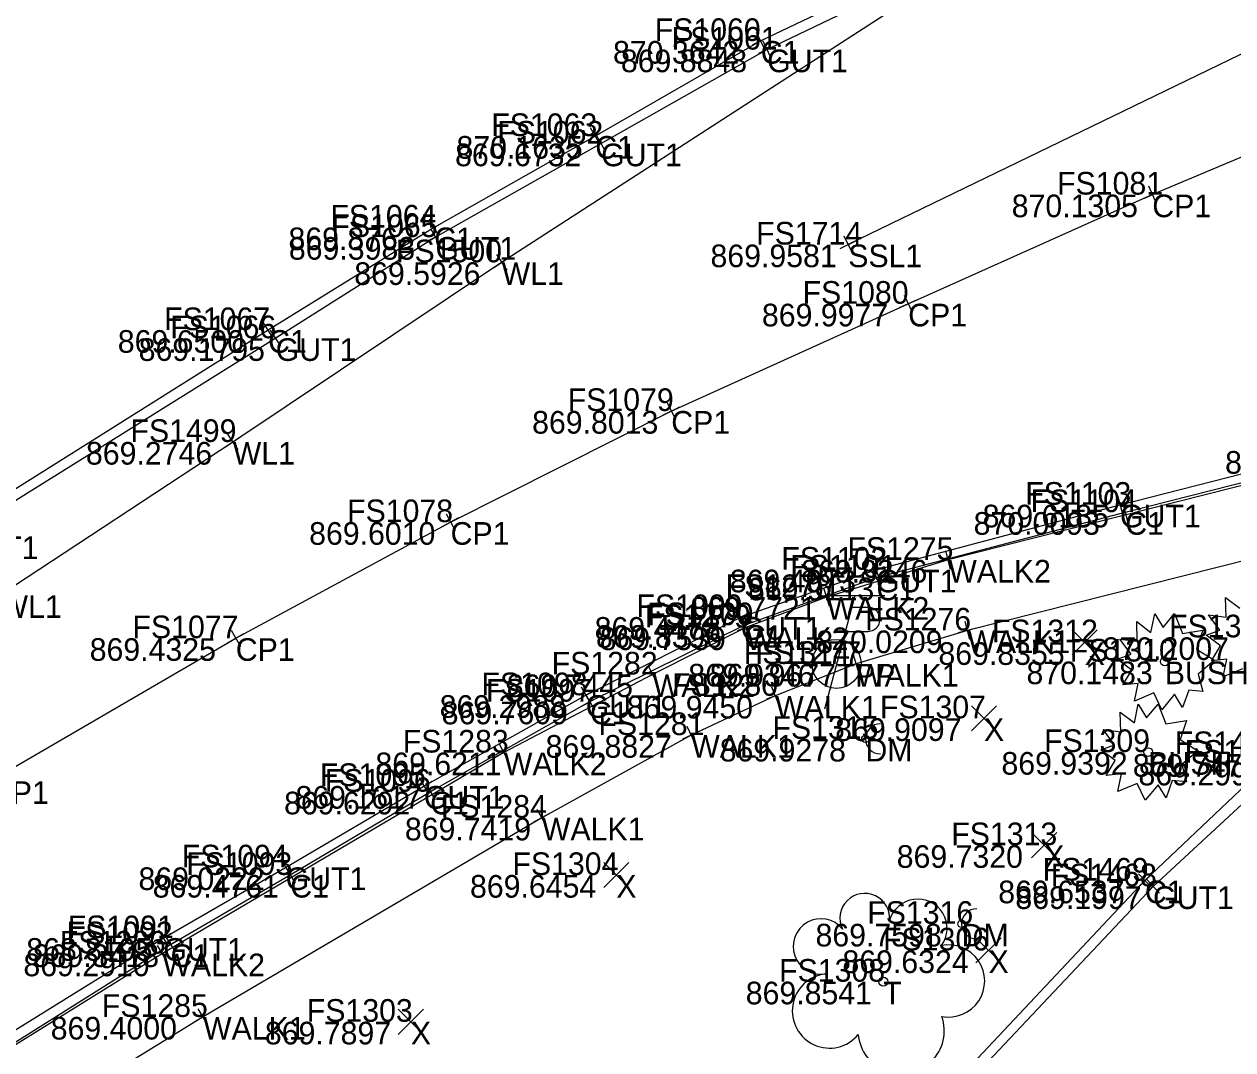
# Model space of a CAD drawing. Extents: x 1469677 to 1493262, y 375219 to 389293.
# Drawn here: x 1479470.9 to 1479535, y 379824.2 to 379878.6 of the extents above; entities that cross this region are included whole.
import ezdxf

# ---------------------------------------------------------------- set-up
doc = ezdxf.new("R2010")
doc.units = 0
for name, color, linetype in [('DR_X_Drive_Pipe', 7, 'Continuous'), ('DV_X_Lot_Line', 7, 'Continuous'), ('DV_X_Text', 7, 'Continuous'), ('GK_Visualization', 7, 'Continuous'), ('PNTELEV', 7, 'Continuous'), ('PNTS', 7, 'Continuous'), ('RD_P_Text', 7, 'Continuous'), ('RD_X_RR_1', 7, 'Continuous'), ('RW_P_Const_Limits', 7, 'Continuous'), ('RW_P_Esmt_SW', 7, 'Continuous'), ('RW_P_Esmt_U', 7, 'Continuous'), ('UT_X_Electric', 7, 'Continuous')]:
    doc.layers.add(name, color=color, linetype=linetype)

msp = doc.modelspace()

# ---------------------------------------------------------------- linework, layer by layer
at = {"layer": 'DR_X_Drive_Pipe'}
msp.add_lwpolyline([(1479451.52, 379837.183), (1479469.615, 379848.276), (1479481.983, 379856.403), (1479496.242, 379865.929), (1479520, 379881.306), (1479538.557, 379892.999), (1479553.442, 379903.409), (1479554.944, 379904.326), (1479564.844, 379911.311), (1479573.24, 379917.005), (1479582.403, 379926.468), (1479585.515, 379929.786), (1479589.646, 379934.736), (1479591.405, 379936.451), (1479593.775, 379939.335)], dxfattribs=at)
at = {"layer": 'DV_X_Lot_Line'}
for points in [[(1479600.533, 379870.639), (1479580.734, 379865.6), (1479561.549, 379860.766), (1479542.709, 379855.919), (1479519.925, 379850.15), (1479513.475, 379848.178), (1479509.191, 379846.568), (1479504.249, 379844.075), (1479496.362, 379839.934), (1479478.251, 379829.275), (1479450.128, 379811.818)], [(1479601.313, 379866.859), (1479581.547, 379861.918), (1479562.5, 379857.02), (1479543.703, 379852.153), (1479520.939, 379846.407), (1479515.035, 379844.634), (1479510.748, 379842.941), (1479506.291, 379840.861), (1479498.375, 379836.478), (1479480.408, 379825.918), (1479452.204, 379808.527)]]:
    msp.add_lwpolyline(points, dxfattribs=at)
at = {"layer": 'PNTELEV'}
for p, q in [((1479510.196, 379877.213), (1479509.764, 379878.116)), ((1479510.431, 379877.88), (1479509.529, 379877.449)), ((1479510.772, 379877.425), (1479509.87, 379876.992)), ((1479509.98, 379877.664), (1479509.98, 379877.664)), ((1479510.538, 379876.758), (1479510.104, 379877.659)), ((1479510.321, 379877.209), (1479510.321, 379877.209)), ((1479501.641, 379872.873), (1479500.773, 379872.375)), ((1479501.456, 379872.191), (1479500.958, 379873.058)), ((1479501.955, 379872.469), (1479501.085, 379871.976)), ((1479501.207, 379872.624), (1479501.207, 379872.624)), ((1479501.766, 379871.788), (1479501.274, 379872.658)), ((1479501.52, 379872.223), (1479501.52, 379872.223)), ((1479530.286, 379869.316), (1479531.198, 379869.724)), ((1479530.538, 379869.976), (1479530.946, 379869.063)), ((1479530.742, 379869.52), (1479530.742, 379869.52)), ((1479493.102, 379868.02), (1479492.232, 379867.526)), ((1479492.914, 379867.339), (1479492.42, 379868.208)), ((1479492.98, 379866.834), (1479492.488, 379867.705)), ((1479492.667, 379867.773), (1479492.667, 379867.773)), ((1479493.17, 379867.515), (1479492.298, 379867.024)), ((1479492.734, 379867.269), (1479492.734, 379867.269)), ((1479515.072, 379867.089), (1479514.172, 379866.652)), ((1479514.84, 379866.421), (1479514.404, 379867.32)), ((1479514.622, 379866.871), (1479514.622, 379866.871)), ((1479495.826, 379865.651), (1479496.658, 379866.207)), ((1479495.964, 379866.345), (1479496.52, 379865.513)), ((1479496.242, 379865.929), (1479496.242, 379865.929)), ((1479517.344, 379863.526), (1479518.256, 379863.938)), ((1479517.594, 379864.188), (1479518.006, 379863.277)), ((1479517.8, 379863.732), (1479517.8, 379863.732)), ((1479484.285, 379862.596), (1479483.435, 379862.07)), ((1479484.123, 379861.908), (1479483.597, 379862.758)), ((1479484.682, 379862.169), (1479483.838, 379861.634)), ((1479483.86, 379862.333), (1479483.86, 379862.333)), ((1479484.528, 379861.479), (1479483.992, 379862.324)), ((1479484.26, 379861.902), (1479484.26, 379861.902)), ((1479504.788, 379857.82), (1479505.682, 379858.27)), ((1479505.01, 379858.491), (1479505.46, 379857.598)), ((1479505.235, 379858.045), (1479505.235, 379858.045)), ((1479481.708, 379856.82), (1479482.258, 379855.985)), ((1479481.565, 379856.128), (1479482.401, 379856.677)), ((1479481.983, 379856.403), (1479481.983, 379856.403)), ((1479528.548, 379852.945), (1479529.514, 379853.202)), ((1479528.902, 379853.557), (1479529.16, 379852.59)), ((1479529.031, 379853.074), (1479529.031, 379853.074)), ((1479529.182, 379853.166), (1479529.436, 379852.199)), ((1479493.095, 379851.915), (1479493.975, 379852.39)), ((1479493.297, 379852.592), (1479493.773, 379851.712)), ((1479528.825, 379852.555), (1479529.793, 379852.81)), ((1479529.309, 379852.683), (1479529.309, 379852.683)), ((1479493.535, 379852.152), (1479493.535, 379852.152)), ((1479520.048, 379849.665), (1479519.802, 379850.635)), ((1479515.615, 379849.465), (1479516.559, 379849.796)), ((1479515.922, 379850.102), (1479516.252, 379849.159)), ((1479520.41, 379850.273), (1479519.44, 379850.027)), ((1479519.925, 379850.15), (1479519.925, 379850.15)), ((1479515.645, 379849.039), (1479516.587, 379849.376)), ((1479515.947, 379849.678), (1479516.285, 379848.737)), ((1479516.087, 379849.631), (1479516.087, 379849.631)), ((1479516.116, 379849.208), (1479516.116, 379849.208)), ((1479513.621, 379847.7), (1479513.329, 379848.657)), ((1479513.953, 379848.325), (1479512.997, 379848.032)), ((1479513.475, 379848.178), (1479513.475, 379848.178)), ((1479508.472, 379846.892), (1479509.364, 379847.342)), ((1479508.693, 379847.563), (1479509.143, 379846.67)), ((1479508.647, 379846.465), (1479509.543, 379846.91)), ((1479509.659, 379846.744), (1479508.723, 379846.392)), ((1479508.873, 379847.136), (1479509.317, 379846.24)), ((1479508.918, 379847.117), (1479508.918, 379847.117)), ((1479509.367, 379846.1), (1479509.015, 379847.036)), ((1479509.095, 379846.688), (1479509.095, 379846.688)), ((1479509.191, 379846.568), (1479509.191, 379846.568)), ((1479521.061, 379845.923), (1479520.817, 379846.892)), ((1479481.712, 379845.746), (1479482.576, 379846.249)), ((1479481.893, 379846.43), (1479482.395, 379845.566)), ((1479482.144, 379845.998), (1479482.144, 379845.998)), ((1479521.424, 379846.53), (1479520.454, 379846.285)), ((1479520.939, 379846.407), (1479520.939, 379846.407)), ((1479515.514, 379844.777), (1479514.556, 379844.49)), ((1479515.179, 379844.155), (1479514.891, 379845.112)), ((1479515.035, 379844.634), (1479515.035, 379844.634)), ((1479504.695, 379844.3), (1479503.803, 379843.85)), ((1479504.474, 379843.628), (1479504.024, 379844.521)), ((1479504.249, 379844.075), (1479504.249, 379844.075)), ((1479500.456, 379843.411), (1479500.946, 379842.539)), ((1479510.932, 379842.476), (1479510.564, 379843.406)), ((1479500.265, 379842.73), (1479501.137, 379843.22)), ((1479500.488, 379842.388), (1479501.36, 379842.879)), ((1479500.678, 379843.069), (1479501.17, 379842.198)), ((1479500.701, 379842.975), (1479500.701, 379842.975)), ((1479511.213, 379843.125), (1479510.283, 379842.758)), ((1479510.748, 379842.941), (1479510.748, 379842.941)), ((1479500.924, 379842.634), (1479500.924, 379842.634)), ((1479506.744, 379841.073), (1479505.838, 379840.65)), ((1479506.502, 379840.408), (1479506.08, 379841.314)), ((1479506.291, 379840.861), (1479506.291, 379840.861)), ((1479496.805, 379840.167), (1479495.919, 379839.702)), ((1479496.594, 379839.491), (1479496.13, 379840.377)), ((1479496.362, 379839.934), (1479496.362, 379839.934)), ((1479491.688, 379837.906), (1479492.55, 379838.414)), ((1479491.865, 379838.591), (1479492.373, 379837.729)), ((1479492.196, 379838.287), (1479492.708, 379837.428)), ((1479492.022, 379837.602), (1479492.882, 379838.113)), ((1479492.119, 379838.16), (1479492.119, 379838.16)), ((1479492.452, 379837.857), (1479492.452, 379837.857)), ((1479498.812, 379836.72), (1479497.938, 379836.235)), ((1479498.617, 379836.04), (1479498.133, 379836.915)), ((1479498.375, 379836.478), (1479498.375, 379836.478)), ((1479484.355, 379833.595), (1479485.221, 379834.095)), ((1479484.538, 379834.278), (1479485.038, 379833.412)), ((1479484.783, 379833.878), (1479485.285, 379833.013)), ((1479484.788, 379833.845), (1479484.788, 379833.845)), ((1479484.601, 379833.195), (1479485.467, 379833.697)), ((1479485.034, 379833.446), (1479485.034, 379833.446)), ((1479530.713, 379833.489), (1479529.987, 379832.801)), ((1479530.694, 379832.782), (1479530.006, 379833.508)), ((1479530.35, 379833.145), (1479530.35, 379833.145)), ((1479531.153, 379833.181), (1479530.419, 379832.502)), ((1479531.126, 379832.474), (1479530.446, 379833.208)), ((1479530.786, 379832.841), (1479530.786, 379832.841)), ((1479478.037, 379830.519), (1479478.563, 379829.669)), ((1479477.875, 379829.831), (1479478.725, 379830.358)), ((1479478.26, 379829.499), (1479479.106, 379830.031)), ((1479478.3, 379830.094), (1479478.3, 379830.094)), ((1479478.417, 379830.188), (1479478.949, 379829.342)), ((1479478.682, 379829.529), (1479477.82, 379829.021)), ((1479478.505, 379828.844), (1479477.997, 379829.706)), ((1479478.251, 379829.275), (1479478.251, 379829.275)), ((1479478.683, 379829.765), (1479478.683, 379829.765)), ((1479480.839, 379826.172), (1479479.977, 379825.665)), ((1479480.661, 379825.487), (1479480.155, 379826.349)), ((1479480.408, 379825.918), (1479480.408, 379825.918))]:
    msp.add_line(p, q, dxfattribs=at)
at = {"layer": 'PNTS'}
for p, q in [((1479514.963, 379848.237), (1479513.357, 379842.237)), ((1479516.563, 379848.237), (1479513.363, 379848.237)), ((1479514.803, 379847.637), (1479515.653, 379847.637)), ((1479514.462, 379846.362), (1479515.653, 379846.362))]:
    msp.add_line(p, q, dxfattribs=at)
for centre, radius in [((1479514, 379844.637), 1.3), ((1479515.532, 379840.661), 0.2), ((1479520.633, 379830.853), 0.2)]:
    msp.add_circle(centre, radius, dxfattribs=at)
for centre, radius, start, end in [((1479515.666, 379847), 0.638, 268.8767, 91.1233), ((1479516.332, 379840.661), 0.8, 90, 270), ((1479521.433, 379830.853), 0.8, 90, 270)]:
    msp.add_arc(centre, radius, start, end, dxfattribs=at)
at = {"layer": 'RD_P_Text'}
for points in [[(1479522.397, 379883.597), (1479509.98, 379877.664), (1479501.207, 379872.624), (1479492.667, 379867.773), (1479483.86, 379862.333), (1479467.175, 379851.843), (1479450.132, 379841.187), (1479435.273, 379831.857)], [(1479522.804, 379883.209), (1479510.321, 379877.209), (1479501.52, 379872.223), (1479492.734, 379867.269), (1479484.26, 379861.902), (1479467.4, 379851.399), (1479450.552, 379840.847), (1479435.368, 379831.41)], [(1479448.263, 379811.446), (1479461.223, 379819.505), (1479478.3, 379830.094), (1479484.788, 379833.845), (1479492.119, 379838.16), (1479500.701, 379842.975), (1479508.918, 379847.117), (1479516.087, 379849.631), (1479529.031, 379853.074), (1479547.645, 379857.817), (1479566.743, 379862.68), (1479585.84, 379867.633), (1479595.941, 379870.21)], [(1479448.497, 379810.926), (1479461.699, 379819.081), (1479478.683, 379829.765), (1479485.034, 379833.446), (1479492.452, 379837.857), (1479500.924, 379842.634), (1479509.095, 379846.688), (1479516.116, 379849.208), (1479529.309, 379852.683), (1479547.62, 379857.33), (1479567.188, 379862.296), (1479585.958, 379867.104), (1479596.074, 379869.801)], [(1479601.319, 379856.892), (1479590.521, 379858.039), (1479580.718, 379858.057), (1479571.147, 379856.791), (1479561.287, 379853.753), (1479553.092, 379850.703), (1479544.73, 379845.631), (1479537.421, 379839.852), (1479530.35, 379833.145), (1479518.148, 379820.183), (1479506.748, 379808.804), (1479505.037, 379808.132), (1479502.743, 379808.986), (1479490.356, 379819.723), (1479452.909, 379780.601)], [(1479601.347, 379856.369), (1479590.364, 379857.442), (1479580.925, 379857.48), (1479571.059, 379856.275), (1479561.558, 379853.273), (1479553.285, 379850.192), (1479545.205, 379845.234), (1479537.871, 379839.395), (1479530.786, 379832.841), (1479518.522, 379819.829), (1479508.592, 379809.053), (1479504.774, 379807.6), (1479502.376, 379808.454), (1479490.367, 379818.943), (1479453.507, 379780.799)]]:
    msp.add_lwpolyline(points, dxfattribs=at)
at = {"layer": 'RD_X_RR_1'}
msp.add_lwpolyline([(1479441.789, 379822.021), (1479455.003, 379829.684), (1479469.105, 379838.412), (1479482.144, 379845.998), (1479493.535, 379852.152), (1479505.235, 379858.045), (1479517.8, 379863.732), (1479530.742, 379869.52), (1479544.647, 379875.382), (1479558.927, 379881.461), (1479574.038, 379887.901), (1479589.196, 379894.597), (1479596.439, 379897.36)], dxfattribs=at)
at = {"layer": 'RW_P_Const_Limits'}
for points in [[(1479535.528, 379844.377), (1479534.508, 379843.947), (1479534.7, 379844.888), (1479533.888, 379844.805), (1479534.362, 379845.595), (1479533.593, 379846.163), (1479534.332, 379846.427), (1479533.725, 379847.23), (1479534.657, 379847.12), (1479534.627, 379848.158), (1479535.38, 379847.59)], [(1479531.318, 379846.57), (1479531.923, 379847.305), (1479532.338, 379846.252), (1479533.43, 379846.432), (1479533.091, 379845.42), (1479534.036, 379844.825), (1479533.18, 379844.09), (1479533.43, 379843.177), (1479532.676, 379843.245), (1479532.351, 379842.332), (1479531.923, 379843.023), (1479531.245, 379842.207), (1479530.816, 379843.093), (1479529.796, 379842.663), (1479529.988, 379843.605), (1479529.176, 379843.522), (1479529.65, 379844.312), (1479528.881, 379844.88), (1479529.62, 379845.143), (1479529.013, 379845.947), (1479529.945, 379845.837), (1479529.915, 379846.875), (1479530.668, 379846.307), (1479530.875, 379847.292), (1479531.318, 379846.57)], [(1479530.444, 379841.773), (1479531.049, 379842.508), (1479531.464, 379841.454), (1479532.556, 379841.634), (1479532.217, 379840.623), (1479533.162, 379840.028), (1479532.306, 379839.293), (1479532.556, 379838.379), (1479531.802, 379838.448), (1479531.477, 379837.534), (1479531.049, 379838.226), (1479530.371, 379837.409), (1479529.942, 379838.296), (1479528.922, 379837.866), (1479529.114, 379838.808), (1479528.302, 379838.724), (1479528.776, 379839.514), (1479528.007, 379840.083), (1479528.746, 379840.346), (1479528.139, 379841.149), (1479529.071, 379841.039), (1479529.041, 379842.078), (1479529.794, 379841.509), (1479530.001, 379842.494), (1479530.444, 379841.773)]]:
    msp.add_lwpolyline(points, dxfattribs=at)
for centre, radius in [((1479531.402, 379844.761), 0.23), ((1479530.528, 379839.963), 0.23), ((1479516.48, 379827.785), 0.24)]:
    msp.add_circle(centre, radius, dxfattribs=at)
for centre, radius, start, end in [((1479515.496, 379831.153), 1.317, 354.0047, 205.97412), ((1479518.306, 379830.614), 1.553, 323.82996, 165.0376), ((1479513.171, 379829.649), 1.471, 39.06254, 279.54124), ((1479519.94, 379827.821), 1.915, 259.14531, 101.45961), ((1479513.627, 379826.237), 1.974, 96.17219, 320.57371), ((1479517.426, 379825.18), 2.284, 184.94757, 19.45715)]:
    msp.add_arc(centre, radius, start, end, dxfattribs=at)
at = {"layer": 'RW_P_Esmt_U'}
for p, q in [((1479526.492, 379845.115), (1479527.826, 379846.45)), ((1479526.492, 379846.45), (1479527.826, 379845.115)), ((1479521.152, 379841.083), (1479522.486, 379842.418)), ((1479521.152, 379842.418), (1479522.486, 379841.083)), ((1479524.346, 379834.355), (1479525.68, 379835.69)), ((1479524.346, 379835.69), (1479525.68, 379834.355)), ((1479501.654, 379832.774), (1479502.988, 379834.109)), ((1479501.654, 379834.109), (1479502.988, 379832.774)), ((1479521.393, 379828.777), (1479522.727, 379830.112)), ((1479521.393, 379830.112), (1479522.727, 379828.777)), ((1479490.759, 379824.993), (1479492.093, 379826.328)), ((1479490.759, 379826.328), (1479492.093, 379824.993))]:
    msp.add_line(p, q, dxfattribs=at)
at = {"layer": 'UT_X_Electric'}
msp.add_lwpolyline([(1479823.042, 380000.22), (1479820.4, 379999.933), (1479798.147, 379991.168), (1479736.037, 379968.233), (1479710.112, 379956.448), (1479679.103, 379944.837), (1479664.157, 379939.675), (1479652.585, 379935.616), (1479645.234, 379932.512), (1479624.647, 379923.417), (1479621.963, 379921.485), (1479620.421, 379921.063), (1479600.276, 379909.045), (1479588.442, 379902.577), (1479565.169, 379891.726), (1479542.109, 379880.195), (1479514.622, 379866.871)], dxfattribs=at)

# ---------------------------------------------------------------- texts
at = {"layer": 'DV_X_Text'}
for s, p in [('870.3642', (1479502.147, 379876.464)), ('869.8848', (1479502.564, 379876.009)), ('869.6732', (1479493.772, 379871.023)), ('870.1635', (1479493.847, 379871.424)), ('870.1305', (1479523.288, 379868.32)), ('869.8762', (1479484.938, 379866.573)), ('869.3983', (1479484.958, 379866.069)), ('869.9581', (1479507.316, 379865.671)), ('869.5926', (1479488.428, 379864.729)), ('869.9977', (1479510.043, 379862.532)), ('869.6500', (1479475.886, 379861.133)), ('869.1795', (1479476.995, 379860.702)), ('869.8013', (1479497.857, 379856.845)), ('869.2746', (1479474.198, 379855.203)), ('870.0020', (1479534.602, 379854.719)), ('869.6185', (1479521.747, 379851.874)), ('870.0093', (1479521.269, 379851.483)), ('869.6010', (1479486.034, 379850.952)), ('869.8246', (1479512.121, 379848.95)), ('869.4973', (1479508.34, 379848.431)), ('869.9113', (1479509.305, 379848.008)), ('869.7721', (1479506.245, 379846.978)), ('869.4478', (1479501.171, 379845.917)), ('869.8396', (1479501.244, 379845.488)), ('869.7539', (1479501.443, 379845.368)), ('869.4325', (1479474.397, 379844.798)), ('870.0209', (1479512.927, 379845.207)), ('870.2007', (1479528.112, 379844.843)), ('869.8355', (1479519.402, 379844.583)), ('869.9346', (1479506.139, 379843.437)), ('869.9677', (1479507.278, 379843.434)), ('870.1483', (1479524.072, 379843.56)), ('869.7445', (1479496.511, 379842.875)), ('869.2988', (1479492.953, 379841.775)), ('869.9450', (1479502.878, 379841.741)), ('869.7609', (1479493.063, 379841.434)), ('869.9097', (1479513.93, 379840.551)), ('869.8827', (1479498.572, 379839.661)), ('869.9278', (1479507.803, 379839.461)), ('869.6211', (1479489.548, 379838.734)), ('869.9392', (1479522.744, 379838.763)), ('869.7473', (1479529.711, 379838.652)), ('869.2990', (1479530.01, 379838.195)), ('869.6292', (1479484.704, 379836.657)), ('869.1617', (1479485.308, 379836.96)), ('869.7419', (1479491.11, 379835.278)), ('869.7320', (1479517.19, 379833.823)), ('869.0222', (1479476.984, 379832.645)), ('869.4761', (1479477.738, 379832.246)), ('869.6454', (1479494.564, 379832.241)), ('869.6537', (1479522.574, 379831.945)), ('869.1997', (1479523.483, 379831.641)), ('869.7598', (1479512.885, 379829.653)), ('868.8195', (1479471.035, 379828.894)), ('869.2910', (1479470.882, 379828.075)), ('869.3418', (1479471.38, 379828.565)), ('869.6324', (1479514.312, 379828.244)), ('869.8541', (1479509.184, 379826.585)), ('869.4000', (1479472.33, 379824.718)), ('869.7897', (1479483.688, 379824.461))]:
    msp.add_text(s, height=1.2, dxfattribs=at).set_placement(p)
at = {"layer": 'GK_Visualization'}
for s, p in [('C1', (1479509.98, 379876.464)), ('GUT1', (1479510.321, 379876.009)), ('C1', (1479501.207, 379871.424)), ('GUT1', (1479501.52, 379871.023)), ('CP1', (1479530.742, 379868.32)), ('C1', (1479492.667, 379866.573)), ('GUT1', (1479492.734, 379866.069)), ('SSL1', (1479514.622, 379865.671)), ('WL1', (1479496.242, 379864.729)), ('CP1', (1479517.8, 379862.532)), ('C1', (1479483.86, 379861.133)), ('GUT1', (1479484.26, 379860.702)), ('CP1', (1479505.235, 379856.845)), ('WL1', (1479481.983, 379855.203)), ('GUT1', (1479529.031, 379851.874)), ('C1', (1479529.309, 379851.483)), ('CP1', (1479493.535, 379850.952)), ('GUT1', (1479467.4, 379850.199)), ('WALK2', (1479519.925, 379848.95)), ('GUT1', (1479516.087, 379848.431)), ('C1', (1479516.116, 379848.008)), ('WL1', (1479469.615, 379847.076)), ('WALK2', (1479513.475, 379846.978)), ('GUT1', (1479508.918, 379845.917)), ('C1', (1479509.095, 379845.488)), ('WALK2', (1479509.191, 379845.368)), ('CP1', (1479482.144, 379844.798)), ('WALK1', (1479520.939, 379845.207)), ('X', (1479527.159, 379844.583)), ('TPP', (1479514, 379843.437)), ('WALK1', (1479515.035, 379843.434)), ('BUSH', (1479531.403, 379843.56)), ('WALK2', (1479504.249, 379842.875)), ('GUT1', (1479500.701, 379841.775)), ('WALK1', (1479510.748, 379841.741)), ('C1', (1479500.924, 379841.434)), ('X', (1479521.819, 379840.551)), ('WALK1', (1479506.291, 379839.661)), ('DM', (1479515.532, 379839.461)), ('WALK2', (1479496.362, 379838.734)), ('BUSH', (1479530.529, 379838.763)), ('CP1', (1479469.105, 379837.212)), ('GUT1', (1479492.119, 379836.96)), ('C1', (1479492.452, 379836.657)), ('WALK1', (1479498.375, 379835.278)), ('X', (1479525.013, 379833.823)), ('GUT1', (1479484.788, 379832.645)), ('C1', (1479485.034, 379832.246)), ('X', (1479502.321, 379832.241)), ('C1', (1479530.35, 379831.945)), ('GUT1', (1479530.786, 379831.641)), ('DM', (1479520.633, 379829.653)), ('GUT1', (1479478.3, 379828.894)), ('WALK2', (1479478.251, 379828.075)), ('C1', (1479478.683, 379828.565)), ('X', (1479522.06, 379828.244)), ('T', (1479516.48, 379826.585)), ('WALK1', (1479480.408, 379824.718)), ('X', (1479491.426, 379824.461))]:
    msp.add_text(s, height=1.2, dxfattribs=at).set_placement(p)
at = {"layer": 'RW_P_Esmt_SW'}
for s, p in [('FS1060', (1479504.359, 379877.664)), ('FS1061', (1479505.255, 379877.209)), ('FS1063', (1479495.69, 379872.624)), ('FS1062', (1479496.012, 379872.223)), ('FS1081', (1479525.695, 379869.52)), ('FS1064', (1479487.159, 379867.773)), ('FS1065', (1479487.217, 379867.269)), ('FS1714', (1479509.739, 379866.871)), ('FS1500', (1479490.64, 379865.929)), ('FS1080', (1479512.198, 379863.732)), ('FS1067', (1479478.343, 379862.333)), ('FS1066', (1479478.667, 379861.902)), ('FS1079', (1479499.746, 379858.045)), ('FS1499', (1479476.56, 379856.403)), ('FS1103', (1479524.006, 379853.074)), ('FS1104', (1479524.293, 379852.683)), ('FS1078', (1479488.046, 379852.152)), ('FS1275', (1479514.578, 379850.15)), ('FS1102', (1479511.071, 379849.631)), ('FS1101', (1479511.542, 379849.208)), ('FS1278', (1479508.119, 379848.178)), ('FS1099', (1479503.391, 379847.117)), ('FS1100', (1479503.966, 379846.688)), ('FS1077', (1479476.665, 379845.998)), ('FS1279', (1479503.835, 379846.568)), ('FS1276', (1479515.516, 379846.407)), ('FS1311', (1479531.636, 379846.043)), ('FS1312', (1479522.238, 379845.783)), ('FS1310', (1479526.368, 379844.76)), ('FS1282', (1479498.893, 379844.075)), ('FS1314', (1479509.079, 379844.637)), ('FS1277', (1479509.688, 379844.634)), ('FS1098', (1479495.174, 379842.975)), ('FS1280', (1479505.278, 379842.941)), ('FS1097', (1479495.407, 379842.634)), ('FS1307', (1479516.302, 379841.751)), ('FS1281', (1479501.376, 379840.861)), ('FS1315', (1479510.601, 379840.661)), ('FS1283', (1479490.996, 379839.934)), ('FS1309', (1479525.002, 379839.963)), ('FS1466', (1479531.932, 379839.852)), ('FS1467', (1479532.458, 379839.395)), ('FS1095', (1479486.602, 379838.16)), ('FS1096', (1479486.859, 379837.857)), ('FS1284', (1479493.019, 379836.478)), ('FS1313', (1479520.082, 379835.023)), ('FS1094', (1479479.28, 379833.845)), ('FS1093', (1479479.517, 379833.446)), ('FS1304', (1479496.813, 379833.441)), ('FS1469', (1479524.927, 379833.145)), ('FS1468', (1479525.363, 379832.841)), ('FS1316', (1479515.627, 379830.853)), ('FS1091', (1479473.234, 379830.094)), ('FS1092', (1479473.175, 379829.765)), ('FS1306', (1479516.467, 379829.444)), ('FS1286', (1479472.81, 379829.275)), ('FS1308', (1479510.953, 379827.785)), ('FS1285', (1479475.042, 379825.918)), ('FS1303', (1479485.909, 379825.661))]:
    msp.add_text(s, height=1.2, dxfattribs=at).set_placement(p)

doc.saveas('drawing.dxf')
